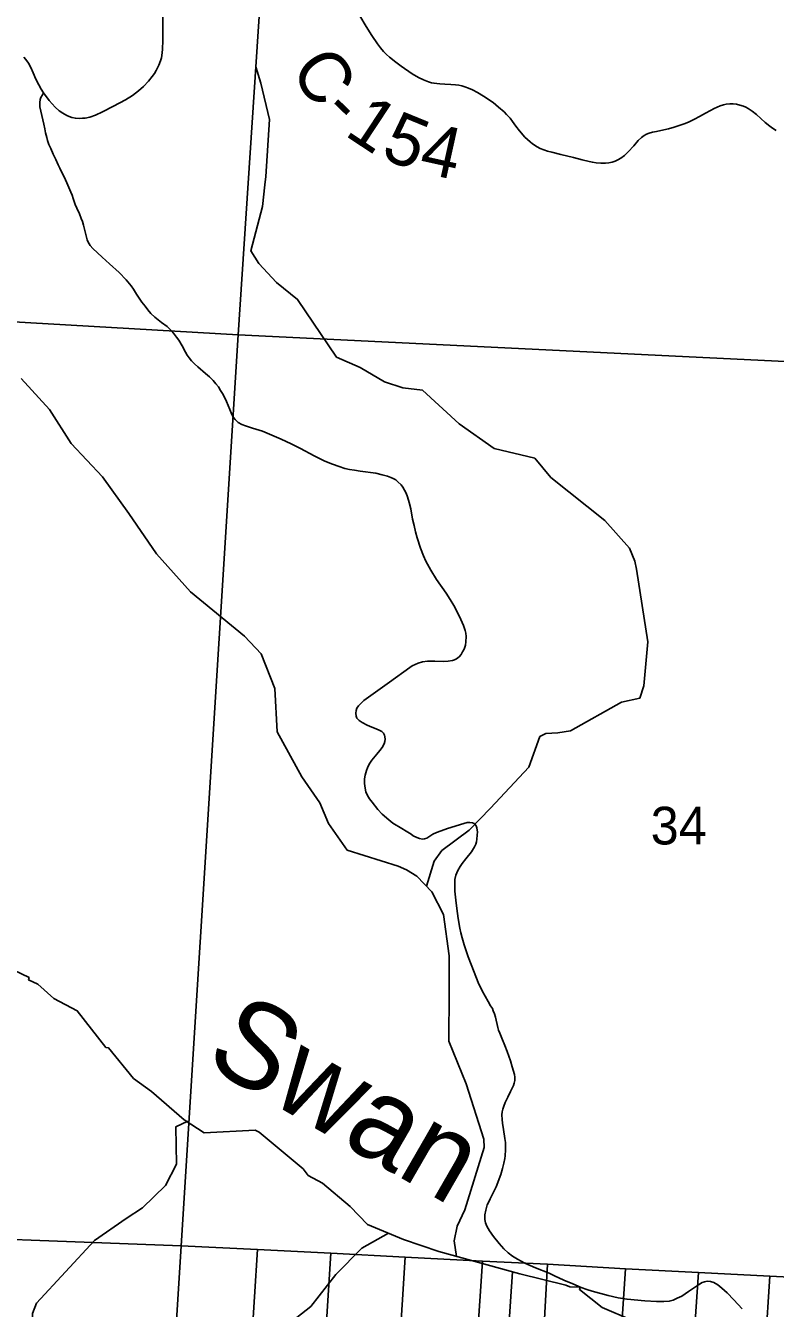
# Model space of a CAD drawing. Extents: x 396.2 to 468.4, y 232.6 to 279.1.
# Drawn here: x 421.121 to 421.953, y 267.097 to 268.52 of the extents above; entities that cross this region are included whole.
import ezdxf

# ---------------------------------------------------------------- set-up
doc = ezdxf.new("R2010")
doc.units = 0
for name, color, linetype in [('GM_X_County_Road', 7, 'Continuous'), ('GM_X_County_Road_Text', 7, 'Continuous'), ('GM_X_Minor_River', 7, 'Continuous'), ('GM_X_Minor_River_Text', 7, 'Continuous'), ('GM_X_Section', 7, 'Continuous'), ('GM_X_Section_Text', 7, 'Continuous'), ('GM_X_Township_Road', 7, 'Continuous')]:
    doc.layers.add(name, color=color, linetype=linetype)

msp = doc.modelspace()

# ---------------------------------------------------------------- linework, layer by layer
at = {"layer": 'GM_X_County_Road'}
for points in [[(421.1189, 268.4851), (421.121, 268.4824), (421.1238, 268.4786), (421.1265, 268.4735), (421.1291, 268.4678), (421.1322, 268.4608), (421.1354, 268.4544), (421.1379, 268.4495), (421.1406, 268.4454), (421.147, 268.4372), (421.1535, 268.4298), (421.158, 268.4257), (421.1619, 268.4229), (421.1667, 268.4203), (421.1691, 268.4192), (421.1722, 268.4182), (421.1761, 268.4173), (421.1803, 268.4171), (421.1838, 268.4173), (421.1867, 268.4176), (421.192, 268.4187), (421.1984, 268.4208), (421.2062, 268.4244), (421.2184, 268.4307), (421.2315, 268.4377), (421.2393, 268.4426), (421.2462, 268.4477), (421.2517, 268.4526), (421.2572, 268.4584), (421.2614, 268.4636), (421.2638, 268.4671), (421.2657, 268.4704), (421.2688, 268.4764), (421.2705, 268.4809), (421.2715, 268.4845), (421.2724, 268.4898), (421.2728, 268.4941), (421.2732, 268.5038), (421.2732, 268.5164), (421.273, 268.5388)], [(421.4918, 268.5309), (421.4987, 268.5191), (421.5049, 268.5091), (421.5112, 268.4998), (421.5146, 268.4955), (421.5181, 268.4915), (421.5215, 268.4879), (421.5247, 268.485), (421.5319, 268.4795), (421.5376, 268.4751), (421.5499, 268.4668), (421.5568, 268.4627), (421.5623, 268.46), (421.568, 268.4577), (421.5712, 268.4568), (421.5742, 268.4562), (421.5774, 268.4558), (421.5804, 268.4555), (421.5862, 268.4552), (421.5928, 268.4548), (421.598, 268.4544), (421.6015, 268.4539), (421.6049, 268.4532), (421.6084, 268.4523), (421.6125, 268.4508), (421.617, 268.4487), (421.6225, 268.4458), (421.629, 268.442), (421.6398, 268.4347), (421.6458, 268.4298), (421.652, 268.4244), (421.6546, 268.4216), (421.6585, 268.4175), (421.6614, 268.4138), (421.6651, 268.4087), (421.669, 268.4035), (421.6751, 268.3964), (421.6778, 268.3938), (421.6807, 268.3912), (421.6834, 268.389), (421.6885, 268.3856), (421.692, 268.3839), (421.6959, 268.3824), (421.7001, 268.3809), (421.705, 268.3797), (421.715, 268.3772), (421.7288, 268.3737), (421.7387, 268.3712), (421.7464, 268.3692), (421.75, 268.3685), (421.754, 268.3679), (421.7591, 268.3676), (421.7645, 268.3676), (421.7681, 268.368), (421.7717, 268.3687), (421.7752, 268.3699), (421.7783, 268.3713), (421.7816, 268.3731), (421.7855, 268.3761), (421.7898, 268.3802), (421.7959, 268.3869), (421.8009, 268.3926), (421.8046, 268.396), (421.8073, 268.3981), (421.8098, 268.3995), (421.8129, 268.4009), (421.8165, 268.4019), (421.8211, 268.4028), (421.8293, 268.4045), (421.8344, 268.4057), (421.8406, 268.4075), (421.8464, 268.4094), (421.8529, 268.4117), (421.8572, 268.4135), (421.8633, 268.4163), (421.8688, 268.4192), (421.8754, 268.4229), (421.8811, 268.4259), (421.8851, 268.4281), (421.8885, 268.4298), (421.8917, 268.4312), (421.8954, 268.4323), (421.8985, 268.4328), (421.9023, 268.4332), (421.9062, 268.4332), (421.9097, 268.4328), (421.9136, 268.4318), (421.9176, 268.4306), (421.9201, 268.4296), (421.9228, 268.4281), (421.9274, 268.4252), (421.9321, 268.4214), (421.9417, 268.4127), (421.9467, 268.4085), (421.95, 268.4062), (421.9539, 268.4038)]]:
    msp.add_lwpolyline(points, dxfattribs=at)
at = {"layer": 'GM_X_Minor_River'}
for points in [[(421.5656, 267.5654), (421.5742, 267.593), (421.5829, 267.6048), (421.613, 267.6274), (421.6368, 267.6517), (421.6794, 267.6974), (421.6914, 267.7312), (421.6983, 267.7348), (421.7116, 267.7355), (421.7256, 267.7377), (421.7821, 267.7693), (421.8027, 267.774), (421.8069, 267.7875), (421.8114, 267.8364), (421.7987, 267.9169), (421.7971, 267.926), (421.7911, 267.9403), (421.7637, 267.9708), (421.7039, 268.0186), (421.686, 268.0401), (421.641, 268.051), (421.6021, 268.0781), (421.5613, 268.1155), (421.5395, 268.1181), (421.5193, 268.1248), (421.4921, 268.1408), (421.466, 268.1523), (421.4226, 268.2163), (421.3994, 268.2349), (421.3796, 268.2561), (421.3706, 268.2704), (421.3838, 268.3193), (421.3864, 268.3436), (421.3874, 268.3526), (421.3916, 268.4159), (421.3819, 268.4561), (421.3764, 268.4745)], [(421.5989, 267.1542), (421.5965, 267.1716), (421.5997, 267.1878), (421.6085, 267.2061), (421.6299, 267.2753), (421.6294, 267.2844), (421.6098, 267.3458), (421.5904, 267.3931), (421.5909, 267.4478), (421.591, 267.488), (421.5845, 267.5338), (421.5716, 267.5589), (421.5552, 267.5765), (421.5436, 267.5833), (421.5343, 267.5874), (421.4778, 267.6052), (421.4568, 267.6347), (421.4472, 267.6578), (421.4273, 267.6865), (421.4001, 267.7364), (421.3974, 267.7847), (421.3823, 267.8231), (421.3637, 267.8427), (421.3039, 267.8917), (421.2662, 267.9339), (421.2355, 267.9789), (421.2061, 268.0194), (421.1713, 268.0565), (421.1471, 268.0942), (421.1157, 268.1286)], [(421.3189, 267.2914), (421.2969, 267.3061), (421.2606, 267.3372), (421.2405, 267.3519), (421.2129, 267.3857), (421.2099, 267.3861), (421.1781, 267.427), (421.152, 267.4407), (421.1342, 267.4566), (421.124, 267.4611), (421.1247, 267.4638), (421.0903, 267.4801), (421.0729, 267.4994), (421.0665, 267.5005), (421.0434, 267.5324), (421.026, 267.5464), (421.0138, 267.5395), (421.0227, 267.5445)], [(421.3007, 267.3044), (421.2874, 267.298), (421.2884, 267.2566), (421.276, 267.2331), (421.2506, 267.2081), (421.2322, 267.1965), (421.1974, 267.1722), (421.1329, 267.1025), (421.1284, 267.0912), (421.1283, 267.0628), (421.129, 267.0103), (421.1055, 266.9351), (421.1086, 266.9115), (421.1099, 266.9039), (421.1009, 266.881), (421.073, 266.8462), (421.0557, 266.8126), (421.0354, 266.7912), (421.0281, 266.7861), (420.9648, 266.743)], [(421.3757, 267.2946), (421.3189, 267.2914)], [(421.7938, 267.0837), (421.7609, 267.0977), (421.7356, 267.1178), (421.7363, 267.1201), (421.725, 267.1205), (421.7204, 267.1223), (421.6694, 267.1352), (421.5794, 267.16), (421.5401, 267.1732), (421.5004, 267.1899), (421.4811, 267.2096), (421.4504, 267.2357), (421.4345, 267.2441), (421.4288, 267.2517), (421.38, 267.2922), (421.3757, 267.2946)], [(421.5237, 267.1801), (421.4939, 267.1635), (421.465, 267.1344), (421.4375, 267.0988), (421.4115, 267.0784), (421.3963, 267.0622), (421.3844, 267.0314), (421.3233, 266.9601), (421.2964, 266.9222), (421.2679, 266.8802), (421.2434, 266.8309), (421.2324, 266.7929), (421.2293, 266.7649), (421.2361, 266.6553)], [(421.6613, 267.1374), (421.6538, 267.0273), (421.6399, 267.0073), (421.6105, 266.9854), (421.5766, 266.9489), (421.5066, 266.8999), (421.4895, 266.8838), (421.4564, 266.8267), (421.4414, 266.7934), (421.4135, 266.7563), (421.4037, 266.7343), (421.4032, 266.7058), (421.4286, 266.6568), (421.4387, 266.642), (421.4616, 266.6238)]]:
    msp.add_lwpolyline(points, dxfattribs=at)
at = {"layer": 'GM_X_Section'}
for points in [[(420.3647, 269.2542), (421.4251, 269.2153), (421.3567, 268.1769), (420.3017, 268.2379)], [(422.4695, 269.1674), (422.4038, 268.126), (421.3567, 268.1769), (421.4251, 269.2153)], [(421.3567, 268.1769), (421.2935, 267.1662), (420.2353, 267.206), (420.2356, 267.2112), (420.2473, 267.3927), (420.2746, 267.8175), (420.3017, 268.2379)], [(422.4038, 268.126), (422.3873, 267.8717), (422.3714, 267.6194), (422.3562, 267.3663), (422.3397, 267.1122), (422.265, 267.1161), (422.1857, 267.1202), (422.1085, 267.1242), (422.0274, 267.1283), (421.9468, 267.1325), (421.8678, 267.1364), (421.7867, 267.1407), (421.6999, 267.1457), (421.6279, 267.1492), (421.5422, 267.1537), (421.4595, 267.1579), (421.3782, 267.1621), (421.2935, 267.1662), (421.3567, 268.1769)], [(420.2353, 267.206), (421.2935, 267.1662), (421.2281, 266.1152), (421.0364, 266.1227), (420.8385, 266.1259), (420.635, 266.1359), (420.4459, 266.1456), (420.2836, 266.1536), (420.1699, 266.1596), (420.221, 266.9787)], [(421.3782, 267.1621), (421.3117, 266.1116), (421.2281, 266.1152), (421.2935, 267.1662)], [(421.4595, 267.1579), (421.3933, 266.1079), (421.3117, 266.1116), (421.3782, 267.1621)], [(421.5422, 267.1537), (421.4762, 266.1071), (421.4761, 266.1042), (421.3933, 266.1079), (421.4595, 267.1579)], [(421.6279, 267.1492), (421.558, 266.1048), (421.5577, 266.1006), (421.4761, 266.1042), (421.4762, 266.1071), (421.5422, 267.1537)], [(421.6999, 267.1457), (421.6427, 266.1001), (421.6425, 266.0968), (421.5577, 266.1006), (421.558, 266.1048), (421.6279, 267.1492)], [(421.7867, 267.1407), (421.7169, 266.0935), (421.6425, 266.0968), (421.6427, 266.1001), (421.6999, 267.1457)], [(421.8678, 267.1364), (421.7962, 266.09), (421.7169, 266.0935), (421.7867, 267.1407)], [(421.9468, 267.1325), (421.8794, 266.0863), (421.8768, 266.0864), (421.7962, 266.09), (421.8678, 267.1364)], [(422.0274, 267.1283), (421.9592, 266.0827), (421.8794, 266.0863), (421.9468, 267.1325)]]:
    msp.add_lwpolyline(points, close=True, dxfattribs=at)
at = {"layer": 'GM_X_Township_Road'}
for points in [[(421.1664, 268.3455), (421.1649, 268.3491), (421.1588, 268.3619), (421.157, 268.3658), (421.1543, 268.3714), (421.1515, 268.3775), (421.1486, 268.3837), (421.1466, 268.3882), (421.145, 268.3925), (421.1442, 268.3958), (421.143, 268.4012), (421.1421, 268.4056), (421.1411, 268.4109), (421.1399, 268.4157), (421.1375, 268.4252), (421.1366, 268.43), (421.1364, 268.435), (421.1369, 268.4381), (421.1378, 268.4403), (421.1396, 268.4435), (421.1406, 268.4454)], [(421.9163, 267.0963), (421.907, 267.1063), (421.8997, 267.114), (421.8937, 267.1192), (421.8892, 267.1229), (421.8846, 267.1255), (421.8812, 267.1264), (421.8773, 267.1268), (421.8744, 267.1263), (421.8716, 267.1253), (421.8677, 267.1227), (421.8567, 267.1154), (421.8492, 267.1103), (421.8442, 267.1079), (421.8397, 267.1059), (421.8352, 267.1047), (421.8293, 267.1042), (421.821, 267.1043), (421.8082, 267.105), (421.7885, 267.1068), (421.7785, 267.1085), (421.7676, 267.1109), (421.7497, 267.1159), (421.7438, 267.1178), (421.7375, 267.12), (421.7281, 267.1238), (421.7181, 267.1281), (421.708, 267.1327), (421.7018, 267.1356), (421.6866, 267.1418), (421.6751, 267.147), (421.6667, 267.1513), (421.6611, 267.1545), (421.6563, 267.1583), (421.6517, 267.1626), (421.6464, 267.1688), (421.6401, 267.1763), (421.6358, 267.1826), (421.6326, 267.188), (421.6312, 267.1915), (421.6306, 267.1955), (421.6305, 267.2006), (421.6315, 267.2057), (421.6332, 267.2115), (421.6348, 267.2151), (421.6364, 267.2184), (421.643, 267.2314), (421.6481, 267.2451), (421.6502, 267.2518), (421.6516, 267.2579), (421.6528, 267.263), (421.6532, 267.266), (421.6535, 267.2728), (421.6535, 267.2808), (421.6529, 267.2854), (421.6512, 267.2951), (421.6501, 267.3022), (421.6497, 267.3063), (421.6494, 267.3115), (421.6499, 267.3149), (421.6504, 267.3176), (421.6516, 267.3212), (421.6531, 267.3251), (421.656, 267.331), (421.6591, 267.3372), (421.6622, 267.3441), (421.6629, 267.3465), (421.6637, 267.3494), (421.664, 267.3532), (421.6634, 267.3563), (421.661, 267.3649), (421.6589, 267.3714), (421.6553, 267.3818), (421.6528, 267.3883), (421.6493, 267.3965), (421.647, 267.4022), (421.6457, 267.4056), (421.6448, 267.4085), (421.6423, 267.42), (421.6412, 267.4236), (421.6399, 267.427), (421.6389, 267.4294), (421.6368, 267.4325), (421.6341, 267.4371), (421.6275, 267.4492), (421.6231, 267.4583), (421.6185, 267.4699), (421.6121, 267.4868), (421.6077, 267.5001), (421.6055, 267.5078), (421.604, 267.5133), (421.6029, 267.5185), (421.6009, 267.5295), (421.5995, 267.5405), (421.5982, 267.5498), (421.5973, 267.5596), (421.5971, 267.5663), (421.5974, 267.5726), (421.5985, 267.5773), (421.5994, 267.58), (421.6007, 267.5827), (421.6032, 267.587), (421.6055, 267.5902), (421.6094, 267.5955), (421.6156, 267.6034), (421.6189, 267.609), (421.6207, 267.612), (421.6214, 267.6143), (421.6217, 267.6173), (421.6221, 267.6217), (421.6222, 267.6254), (421.622, 267.6274), (421.6216, 267.63), (421.6209, 267.6321), (421.6198, 267.6336), (421.6185, 267.6347), (421.617, 267.6355), (421.614, 267.6359), (421.6109, 267.6357), (421.6072, 267.6347), (421.5889, 267.6291), (421.5821, 267.6267), (421.577, 267.6247), (421.5727, 267.6229), (421.5661, 267.6186), (421.5637, 267.6178), (421.5612, 267.6174), (421.5581, 267.618), (421.555, 267.6191), (421.5511, 267.6211), (421.5486, 267.6229), (421.5433, 267.6263), (421.5383, 267.6292), (421.5284, 267.6352), (421.5238, 267.6388), (421.5164, 267.6451), (421.5117, 267.6504), (421.5053, 267.6586), (421.5025, 267.6621), (421.5001, 267.666), (421.4983, 267.6698), (421.4975, 267.6739), (421.4968, 267.6791), (421.497, 267.6843), (421.4975, 267.6884), (421.499, 267.6936), (421.5002, 267.6967), (421.5022, 267.7005), (421.5052, 267.7051), (421.5108, 267.7117), (421.5141, 267.7156), (421.5166, 267.7191), (421.5186, 267.723), (421.5195, 267.7259), (421.5198, 267.7285), (421.5195, 267.7309), (421.519, 267.7328), (421.518, 267.735), (421.5162, 267.7368), (421.5139, 267.7381), (421.5098, 267.7399), (421.5051, 267.7417), (421.4999, 267.7437), (421.4942, 267.7467), (421.491, 267.7489), (421.4898, 267.7503), (421.4886, 267.7517), (421.4878, 267.7537), (421.4874, 267.7572), (421.4876, 267.76), (421.4886, 267.7626), (421.4902, 267.7655), (421.4924, 267.7676), (421.4961, 267.7711), (421.5247, 267.7917), (421.5472, 267.8079), (421.5497, 267.8096), (421.5532, 267.8113), (421.5565, 267.8128), (421.5614, 267.8142), (421.5669, 267.8148), (421.5749, 267.8148), (421.5844, 267.8147), (421.59, 267.8149), (421.5945, 267.8157), (421.5967, 267.8163), (421.5989, 267.8175), (421.602, 267.8197), (421.6044, 267.8224), (421.6059, 267.8251), (421.6075, 267.8283), (421.6089, 267.8326), (421.6096, 267.8365), (421.6099, 267.8424), (421.6095, 267.8458), (421.6088, 267.8491), (421.607, 267.8543), (421.604, 267.8612), (421.5991, 267.8713), (421.596, 267.8766), (421.5921, 267.8834), (421.5877, 267.8903), (421.5768, 267.9056), (421.5706, 267.9158), (421.5652, 267.9259), (421.5625, 267.9317), (421.5592, 267.9401), (421.5555, 267.9519), (421.5537, 267.9585), (421.5519, 267.9656), (421.5504, 267.9726), (421.5482, 267.9838), (421.5466, 267.9911), (421.5448, 267.9972), (421.5432, 268.0014), (421.5414, 268.0048), (421.5394, 268.008), (421.5376, 268.0104), (421.5341, 268.014), (421.5316, 268.016), (421.5289, 268.0175), (421.5262, 268.0187), (421.5225, 268.02), (421.5166, 268.0218), (421.5097, 268.0234), (421.4923, 268.0258), (421.486, 268.0267), (421.4804, 268.0276), (421.475, 268.0288), (421.4687, 268.0308), (421.4614, 268.0334), (421.453, 268.037), (421.4411, 268.0427), (421.4258, 268.051), (421.4156, 268.0559), (421.4043, 268.0611), (421.3916, 268.0667), (421.3836, 268.0701), (421.3728, 268.0736), (421.365, 268.0759), (421.3606, 268.0776), (421.3566, 268.0799), (421.3535, 268.0829), (421.3512, 268.0857), (421.3498, 268.0886), (421.3473, 268.0941), (421.3438, 268.1029), (421.3417, 268.1077), (421.3394, 268.1119), (421.3372, 268.1154), (421.3347, 268.1192), (421.332, 268.1225), (421.3288, 268.1264), (421.3247, 268.1305), (421.3204, 268.1342), (421.3118, 268.1414), (421.3081, 268.1447), (421.3048, 268.1482), (421.3022, 268.1516), (421.3002, 268.1544), (421.2982, 268.1579), (421.2944, 268.1647), (421.2908, 268.171), (421.2884, 268.1743), (421.2851, 268.1787), (421.2829, 268.1811), (421.2801, 268.184), (421.2778, 268.1861), (421.2717, 268.1908), (421.2642, 268.1965), (421.2596, 268.2008), (421.2563, 268.2049), (421.2534, 268.2087), (421.2499, 268.2134), (421.244, 268.2221), (421.2404, 268.2277), (421.2379, 268.2313), (421.2324, 268.2381), (421.2245, 268.2461), (421.214, 268.2559), (421.2057, 268.2633), (421.1954, 268.2727), (421.1924, 268.2763), (421.1903, 268.2799), (421.1891, 268.2826), (421.1882, 268.2853), (421.1861, 268.2943), (421.185, 268.2986), (421.1839, 268.3026), (421.1826, 268.3062), (421.1806, 268.3114), (421.1776, 268.3175), (421.1757, 268.3215), (421.1746, 268.3249), (421.1736, 268.3282), (421.1723, 268.332), (421.1708, 268.3354), (421.1664, 268.3455)]]:
    msp.add_lwpolyline(points, dxfattribs=at)

# ---------------------------------------------------------------- texts
at = {"layer": 'GM_X_County_Road_Text'}
for s, rotation, p in [('C', 304.4998, (421.4133, 268.4706)), ('-', 316.1355, (421.4479, 268.4225)), ('1', 326.5173, (421.4735, 268.3993)), ('5', 337.7555, (421.5134, 268.3743)), ('4', 347.5203, (421.5559, 268.3579))]:
    msp.add_text(s, height=0.0568, rotation=rotation, dxfattribs=at).set_placement(p)
at = {"layer": 'GM_X_Minor_River_Text'}
msp.add_text('Swan', height=0.0947, rotation=329.9982, dxfattribs=at).set_placement((421.317, 267.3687))
at = {"layer": 'GM_X_Section_Text'}
msp.add_text('34', height=0.04186, rotation=0, dxfattribs=at).set_placement((421.8146, 267.6115))

doc.saveas('drawing.dxf')
